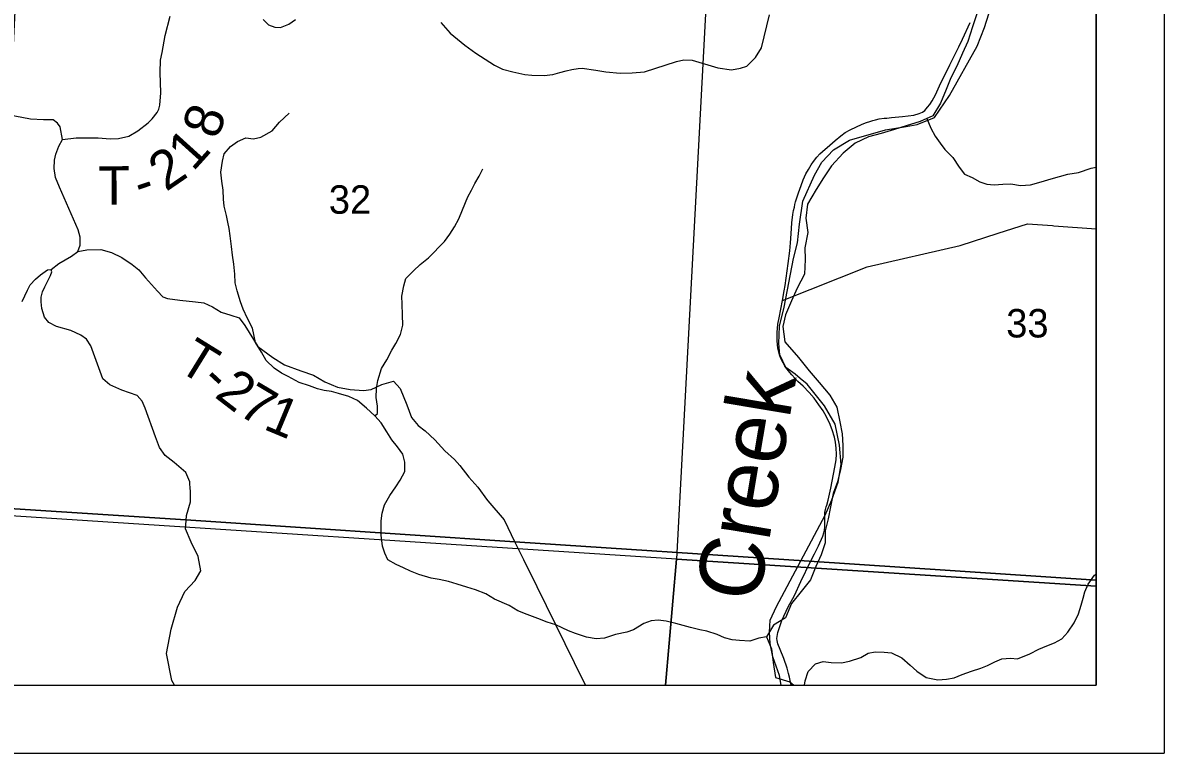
# Model space of a CAD drawing. Extents: x 0 to 44, y -23.8 to 22.
# Drawn here: x 7.321 to 9, y 14 to 15.074 of the extents above; entities that cross this region are included whole.
import ezdxf

# ---------------------------------------------------------------- set-up
doc = ezdxf.new("R2010")
doc.units = 0
for name, color, linetype in [('Default', 7, 'Continuous'), ('GM_X_County_Road', 7, 'Continuous'), ('GM_X_Minor_River', 7, 'Continuous'), ('GM_X_Minor_River_Text', 7, 'Continuous'), ('GM_X_Rail_Line', 7, 'Continuous'), ('GM_X_Section', 7, 'Continuous'), ('GM_X_Section_Text', 7, 'Continuous'), ('GM_X_State_Route', 7, 'Continuous'), ('GM_X_Township_Road', 7, 'Continuous'), ('GM_X_Township_Road_Text', 7, 'Continuous'), ('SH_Cut_Line', 7, 'Continuous'), ('SH_Data', 7, 'Continuous')]:
    doc.layers.add(name, color=color, linetype=linetype)

msp = doc.modelspace()

# ---------------------------------------------------------------- linework, layer by layer
at = {"layer": 'Default'}
msp.add_lwpolyline([(7.2787, 14.3616), (7.5613, 14.343), (8.045, 14.3111), (8.4778, 14.2825), (8.9, 14.2547), (8.9, 20.3521), (8.6785, 20.3684), (7.6577, 20.4476), (7.4495, 20.4611), (7.016, 20.4891)], dxfattribs=at)
for points in [[(8.9, 14.2455), (8.9, 15.2663), (8.3369, 15.3004), (8.2829, 14.2852)], [(7.2659, 14.1), (8.9, 14.1), (8.9, 14.2547), (8.4778, 14.2825), (8.045, 14.3111), (7.5613, 14.343), (7.2787, 14.3616)], [(7.2605, 14.1), (8.2666, 14.1), (8.2829, 14.2852), (7.2726, 14.3512)], [(8.2666, 14.1), (8.9, 14.1), (8.9, 14.2455), (8.2829, 14.2852)]]:
    msp.add_lwpolyline(points, close=True, dxfattribs=at)
at = {"layer": 'GM_X_County_Road'}
for points in [[(7.567, 14.3962), (7.5668, 14.3991), (7.5612, 14.4128), (7.5439, 14.4277), (7.5307, 14.4381), (7.5224, 14.4495), (7.5164, 14.4651), (7.5015, 14.5074), (7.4971, 14.5177), (7.4895, 14.5261), (7.4668, 14.5342), (7.4491, 14.5419), (7.4392, 14.5507), (7.4213, 14.5993), (7.4152, 14.6089), (7.4067, 14.615), (7.3918, 14.6215), (7.3711, 14.6276), (7.3596, 14.6334), (7.3531, 14.6414), (7.3492, 14.6541), (7.3482, 14.664), (7.3483, 14.6707), (7.3502, 14.6788), (7.3539, 14.6862), (7.3619, 14.7026), (7.3639, 14.708), (7.3632, 14.7117)], [(7.5445, 14.1), (7.5407, 14.1068), (7.5329, 14.1464), (7.5396, 14.1824), (7.5486, 14.2146), (7.5597, 14.2377), (7.5746, 14.254), (7.583, 14.268), (7.5794, 14.2893), (7.5689, 14.3106), (7.5607, 14.33), (7.5615, 14.3425), (7.562, 14.3494), (7.5678, 14.3699), (7.5679, 14.3847), (7.5675, 14.3905), (7.567, 14.3962)]]:
    msp.add_lwpolyline(points, dxfattribs=at)
at = {"layer": 'GM_X_Minor_River'}
for points in [[(8.7244, 15.0875), (8.7183, 15.0685), (8.7111, 15.0468), (8.7035, 15.0297), (8.6951, 15.0107), (8.6864, 14.9936), (8.6795, 14.9761), (8.6708, 14.9563), (8.6597, 14.9377), (8.6412, 14.9294), (8.6207, 14.9229), (8.6033, 14.9172), (8.584, 14.9115), (8.565, 14.9066), (8.5457, 14.8971), (8.5279, 14.8827), (8.5108, 14.8641), (8.499, 14.8462), (8.488, 14.8291), (8.4755, 14.8074), (8.4731, 14.7869), (8.4757, 14.766), (8.4715, 14.7435), (8.4719, 14.726), (8.4711, 14.7044), (8.4604, 14.6842), (8.4517, 14.6656), (8.4433, 14.6447), (8.4391, 14.6276), (8.4421, 14.6051), (8.4624, 14.5819), (8.4779, 14.5625), (8.4926, 14.5454), (8.5081, 14.5267), (8.5187, 14.5089), (8.5232, 14.4876), (8.5265, 14.4697), (8.5273, 14.4526), (8.5272, 14.4354), (8.5238, 14.4172), (8.5196, 14.3989), (8.5131, 14.3818), (8.5093, 14.3624), (8.5058, 14.3446), (8.5016, 14.3271), (8.5016, 14.3092), (8.4955, 14.2917), (8.4875, 14.2746), (8.4799, 14.2548), (8.4662, 14.2377), (8.4518, 14.2202), (8.443, 14.1993), (8.4256, 14.1883), (8.4153, 14.1712), (8.4225, 14.1533), (8.4251, 14.1332), (8.4284, 14.1115), (8.4492, 14.105), (8.4552, 14.1)], [(7.6608, 14.9038), (7.6714, 14.9061), (7.688, 14.9156), (7.699, 14.9281), (7.713, 14.9414)], [(8.6508, 14.9337), (8.657, 14.9196), (8.663, 14.9074), (8.6706, 14.8975), (8.6774, 14.888), (8.6891, 14.8762), (8.6985, 14.8618), (8.7064, 14.8515), (8.7174, 14.8469), (8.7287, 14.8404), (8.7393, 14.837), (8.7499, 14.8358), (8.7628, 14.8369), (8.7745, 14.8376), (8.7885, 14.8349), (8.8033, 14.836), (8.8192, 14.8405), (8.8339, 14.845), (8.8582, 14.8517), (8.8741, 14.8543), (8.8926, 14.8607), (8.9, 14.862)], [(8.4153, 14.1712), (8.4038, 14.1692), (8.3906, 14.1646), (8.3755, 14.1658), (8.3645, 14.1669), (8.3535, 14.1695), (8.3426, 14.1745), (8.3275, 14.1794), (8.3173, 14.1813), (8.3033, 14.1847), (8.2927, 14.1877), (8.2817, 14.1907), (8.2677, 14.1941), (8.2556, 14.1956), (8.2454, 14.1949), (8.2345, 14.1907), (8.2197, 14.1816), (8.2099, 14.1782), (8.1929, 14.1744), (8.177, 14.1694), (8.1645, 14.1683), (8.1506, 14.1705), (8.1343, 14.1762), (8.1237, 14.18), (8.1052, 14.1887), (8.0927, 14.1929), (8.0787, 14.1982), (8.0632, 14.2042), (8.0496, 14.2095), (8.0364, 14.2171), (8.0149, 14.2266), (8.0024, 14.2342), (7.9869, 14.2402), (7.9744, 14.2444), (7.9604, 14.2486), (7.9472, 14.2527), (7.9336, 14.2554), (7.9219, 14.2576), (7.9037, 14.2629), (7.8916, 14.2675), (7.8814, 14.2724), (7.8705, 14.2773), (7.8584, 14.2845), (7.8538, 14.2944), (7.8504, 14.3046), (7.8486, 14.3209), (7.8482, 14.3304), (7.8486, 14.3418), (7.8501, 14.3532), (7.8535, 14.3653), (7.861, 14.379), (7.8701, 14.3919), (7.8765, 14.4017), (7.8833, 14.4143), (7.8834, 14.4279), (7.8803, 14.4397), (7.8724, 14.4507), (7.8641, 14.4609), (7.8569, 14.4727), (7.8482, 14.4859), (7.8391, 14.4962), (7.827, 14.5075), (7.8134, 14.5189), (7.801, 14.5246), (7.7855, 14.5291), (7.7753, 14.5318), (7.7647, 14.5333), (7.7548, 14.5359), (7.7428, 14.5405), (7.7276, 14.5454), (7.7114, 14.5541), (7.7016, 14.559), (7.691, 14.5662), (7.6793, 14.5776), (7.6725, 14.5901), (7.6634, 14.6042), (7.6592, 14.625), (7.6517, 14.6394), (7.6453, 14.6531), (7.6415, 14.6637), (7.6366, 14.68), (7.6339, 14.6921), (7.6332, 14.7046), (7.6317, 14.7194), (7.6298, 14.7327), (7.6283, 14.7452), (7.6264, 14.7612), (7.6249, 14.7718), (7.623, 14.7813), (7.6211, 14.7911), (7.6173, 14.8044), (7.6166, 14.815), (7.6158, 14.8283), (7.6139, 14.8416), (7.6124, 14.8545), (7.6151, 14.8708), (7.6177, 14.8814), (7.6268, 14.8924), (7.637, 14.8996), (7.6491, 14.9053), (7.6608, 14.9038)], [(7.8391, 14.4962), (7.8429, 14.4996), (7.8429, 14.5106), (7.841, 14.5231), (7.8414, 14.5364), (7.8433, 14.5481), (7.849, 14.566), (7.8569, 14.5785), (7.8641, 14.5929), (7.8702, 14.6024), (7.8766, 14.6161), (7.8804, 14.6297), (7.88, 14.6449), (7.8792, 14.6604), (7.8789, 14.6722), (7.8815, 14.6874), (7.8849, 14.6984), (7.8959, 14.7097), (7.9057, 14.7189), (7.9178, 14.7287), (7.9416, 14.7526), (7.9496, 14.7633), (7.956, 14.7743), (7.9624, 14.786), (7.9681, 14.7993), (7.976, 14.8183), (7.9813, 14.8281), (7.9863, 14.838), (7.9927, 14.849), (7.998, 14.8596)], [(8.4712, 14.1), (8.4718, 14.1063), (8.4764, 14.1199), (8.4873, 14.1313), (8.4987, 14.1347), (8.5104, 14.1332), (8.5255, 14.1329), (8.5372, 14.1355), (8.5539, 14.1405), (8.5648, 14.1469), (8.5747, 14.1492), (8.5883, 14.1484), (8.5992, 14.1477), (8.614, 14.1401), (8.6265, 14.1295), (8.6363, 14.1208), (8.6499, 14.1113), (8.6669, 14.1079), (8.6801, 14.1087), (8.6911, 14.111), (8.7028, 14.1155), (8.7164, 14.1208), (8.7304, 14.125), (8.7402, 14.1292), (8.7508, 14.1345), (8.7614, 14.1387), (8.7739, 14.1398), (8.7845, 14.1387), (8.8022, 14.1459), (8.8158, 14.1528), (8.8276, 14.1581), (8.8389, 14.1623), (8.8495, 14.1683), (8.8582, 14.1782), (8.8676, 14.1919), (8.8741, 14.2048), (8.8778, 14.2177), (8.8809, 14.2279), (8.8835, 14.2374), (8.8881, 14.2488), (8.8975, 14.2617), (8.9, 14.2634)]]:
    msp.add_lwpolyline(points, dxfattribs=at)
at = {"layer": 'GM_X_Rail_Line'}
msp.add_lwpolyline([(8.4367, 14.1), (8.434, 14.1144), (8.4243, 14.1418), (8.4203, 14.1611), (8.4195, 14.178), (8.4203, 14.1957), (8.43, 14.2158), (8.5015, 14.3502), (8.5112, 14.3728), (8.5204, 14.3988), (8.5249, 14.4246), (8.5225, 14.4529), (8.5159, 14.4841), (8.5005, 14.5111), (8.4748, 14.5426), (8.4648, 14.5513), (8.4572, 14.5573), (8.4436, 14.5675), (8.4348, 14.586), (8.4333, 14.6026), (8.434, 14.6279), (8.4412, 14.6561), (8.4549, 14.7277), (8.4606, 14.7506), (8.4636, 14.7784), (8.4686, 14.8122), (8.4858, 14.8504), (8.4967, 14.8693), (8.5139, 14.8876), (8.5371, 14.9018), (8.5903, 14.9168), (8.6207, 14.922), (8.6365, 14.9249), (8.6624, 14.9353), (8.6841, 14.9675), (8.7252, 15.04), (8.7356, 15.0673), (8.7519, 15.1189)], dxfattribs=at)
at = {"layer": 'GM_X_Section'}
msp.add_lwpolyline([(8.3369, 15.3004), (8.2829, 14.2852), (7.2726, 14.3512), (7.3239, 15.368)], close=True, dxfattribs=at)
at = {"layer": 'GM_X_State_Route'}
for points in [[(7.3632, 14.7117), (7.3742, 14.7201), (7.3927, 14.7313), (7.4021, 14.738), (7.4058, 14.7474), (7.4058, 14.7589), (7.4029, 14.7699), (7.3751, 14.8326), (7.3693, 14.8466), (7.3673, 14.8602), (7.368, 14.8723), (7.3699, 14.8811), (7.3742, 14.893), (7.3797, 14.9029), (7.3763, 14.9215), (7.3723, 14.9269), (7.3662, 14.9316), (7.3517, 14.9316), (7.3328, 14.9327), (7.2757, 14.9436)], [(7.3206, 14.6643), (7.328, 14.6811), (7.332, 14.6887), (7.3401, 14.6971), (7.3473, 14.7034), (7.3576, 14.7108), (7.3632, 14.7117)]]:
    msp.add_lwpolyline(points, dxfattribs=at)
at = {"layer": 'GM_X_Township_Road'}
for p, q in [((8.8379, 14.7758), (8.9, 14.7715)), ((8.0912, 14.217), (8.1461, 14.1054)), ((8.1461, 14.1054), (8.1487, 14.1))]:
    msp.add_line(p, q, dxfattribs=at)
for points in [[(7.3797, 14.9029), (7.4, 14.9053), (7.432, 14.9053), (7.4498, 14.9035), (7.4623, 14.9041), (7.4772, 14.9075), (7.4906, 14.9153), (7.5058, 14.9272), (7.5115, 14.9331), (7.5188, 14.9424), (7.5216, 14.9474), (7.5228, 14.9533), (7.5245, 14.9712), (7.5232, 15.0013), (7.5239, 15.0192), (7.5262, 15.0305), (7.5305, 15.0557), (7.5381, 15.0842)], [(7.675, 15.0792), (7.6829, 15.0713), (7.692, 15.068), (7.7004, 15.0674), (7.7124, 15.0725), (7.7222, 15.0791)], [(7.936, 15.0749), (7.9501, 15.0591), (7.9714, 15.0417), (7.9877, 15.0297), (8.0149, 15.0118), (8.0266, 15.0061), (8.0422, 15.0024), (8.0598, 14.9984), (8.0702, 14.9971), (8.0883, 14.9966), (8.101, 14.9982), (8.1114, 15.0011), (8.1204, 15.0038), (8.1289, 15.0056), (8.1383, 15.0072), (8.1438, 15.0074), (8.1643, 15.0045), (8.179, 15.002), (8.1998, 15.0001), (8.2175, 15.0007), (8.2359, 15.0022), (8.2829, 15.0172), (8.2937, 15.0199), (8.3059, 15.0196), (8.3437, 15.0082), (8.3638, 15.0052), (8.377, 15.0074), (8.386, 15.0107), (8.3988, 15.0231), (8.408, 15.0373), (8.4195, 15.0861)], [(8.4658, 14.2524), (8.4797, 14.2819), (8.4856, 14.2931), (8.4918, 14.305), (8.498, 14.3192), (8.4996, 14.3243), (8.5003, 14.3279), (8.5007, 14.3331), (8.5008, 14.3418), (8.5008, 14.3497), (8.501, 14.354), (8.502, 14.3585), (8.5027, 14.3626), (8.5037, 14.365), (8.5056, 14.3724), (8.5098, 14.39), (8.5157, 14.4205), (8.5177, 14.4316), (8.518, 14.44), (8.5178, 14.4488), (8.5167, 14.4575), (8.5149, 14.465), (8.5117, 14.4756), (8.5079, 14.4859), (8.501, 14.4992), (8.4985, 14.5035), (8.4923, 14.5125), (8.4854, 14.522), (8.4777, 14.5303), (8.4689, 14.5397), (8.4613, 14.5467), (8.4567, 14.5518), (8.4524, 14.5563), (8.4492, 14.5602), (8.4453, 14.565), (8.4423, 14.5695), (8.4394, 14.5743), (8.4363, 14.5806), (8.4342, 14.5861), (8.4319, 14.5959), (8.4312, 14.6011), (8.4308, 14.6064), (8.4306, 14.6101), (8.4306, 14.614), (8.4307, 14.6187), (8.4311, 14.6253), (8.4319, 14.6312), (8.4337, 14.6403), (8.4386, 14.6658), (8.4412, 14.6799), (8.4425, 14.6881), (8.4456, 14.7096), (8.4471, 14.7203), (8.4493, 14.7388), (8.4505, 14.7505), (8.4514, 14.7639), (8.4525, 14.78), (8.454, 14.7923), (8.455, 14.7985), (8.4562, 14.8034), (8.457, 14.8071), (8.458, 14.8108), (8.4624, 14.8242), (8.4662, 14.8348), (8.4692, 14.8432), (8.473, 14.8521), (8.4767, 14.8587), (8.4806, 14.8653), (8.4842, 14.8705), (8.4892, 14.8767), (8.4937, 14.8816), (8.5012, 14.8885), (8.5044, 14.8911), (8.5163, 14.9014), (8.5245, 14.9082), (8.5309, 14.9128), (8.5381, 14.9169), (8.556, 14.9255), (8.562, 14.9278), (8.5669, 14.9293), (8.5713, 14.9306), (8.5753, 14.9317), (8.581, 14.9329), (8.5883, 14.9339), (8.592, 14.9343), (8.5991, 14.9349), (8.6149, 14.9365), (8.6317, 14.9387), (8.6398, 14.9409), (8.6444, 14.9431), (8.6482, 14.9454), (8.6521, 14.9502), (8.6555, 14.954), (8.659, 14.9595), (8.6637, 14.9686), (8.6697, 14.9816), (8.6849, 15.0127), (8.6978, 15.039), (8.7033, 15.0505), (8.7149, 15.0747)], [(8.4386, 14.6658), (8.5634, 14.7155), (8.7001, 14.747), (8.756, 14.7649), (8.7989, 14.7786), (8.836, 14.776), (8.8379, 14.7758)], [(7.4021, 14.738), (7.4157, 14.7405), (7.4361, 14.7407), (7.4516, 14.7365), (7.4669, 14.729), (7.4824, 14.719), (7.4918, 14.711), (7.5018, 14.6993), (7.5194, 14.6797), (7.5273, 14.6713), (7.534, 14.6686), (7.5524, 14.6664), (7.5754, 14.6641), (7.5877, 14.6625), (7.6003, 14.6564), (7.6133, 14.6487), (7.6275, 14.6445), (7.6394, 14.6403), (7.6479, 14.6292), (7.6671, 14.5983), (7.689, 14.5818), (7.706, 14.5711), (7.7302, 14.5626), (7.7491, 14.556), (7.7654, 14.546), (7.7843, 14.5383), (7.8029, 14.5348), (7.8222, 14.5335), (7.8336, 14.535), (7.8496, 14.5425), (7.8663, 14.5473), (7.8761, 14.5366), (7.8861, 14.5126), (7.8929, 14.494), (7.9026, 14.4821), (7.9132, 14.4741), (7.9275, 14.4611), (7.9422, 14.4447), (7.9562, 14.4321), (7.9641, 14.4233), (7.9772, 14.4061), (7.9904, 14.3912), (8.0047, 14.3718), (8.0053, 14.3711), (8.0292, 14.3431), (8.0452, 14.3106), (8.0578, 14.285), (8.0772, 14.2454), (8.0912, 14.217)], [(8.4513, 14.1), (8.4504, 14.1044), (8.4489, 14.1116), (8.4477, 14.1171), (8.4455, 14.1252), (8.4404, 14.1391), (8.435, 14.1526), (8.4317, 14.1606), (8.4306, 14.1656), (8.4303, 14.1685), (8.4308, 14.1715), (8.4318, 14.1774), (8.4345, 14.1864), (8.4378, 14.1954), (8.447, 14.2151), (8.4562, 14.2319), (8.4658, 14.2524)]]:
    msp.add_lwpolyline(points, dxfattribs=at)
at = {"layer": 'SH_Cut_Line'}
msp.add_lwpolyline([(2.838, 14.1), (8.9, 14.1), (8.9, 20.9), (6.8158, 20.9)], dxfattribs=at)
at = {"layer": 'SH_Data'}
for p, q in [((9, 21), (9, 14)), ((8.9, 20.9), (8.9, 14.1)), ((2.1, 14.1), (8.9, 14.1)), ((2, 14), (9, 14))]:
    msp.add_line(p, q, dxfattribs=at)

# ---------------------------------------------------------------- texts
at = {"layer": 'GM_X_Minor_River_Text'}
msp.add_text('Creek', height=0.0947, rotation=80.4921, dxfattribs=at).set_placement((8.4035, 14.2196))
at = {"layer": 'GM_X_Section_Text'}
for s, p in [('32', (7.7714, 14.7935)), ('33', (8.7677, 14.6115))]:
    msp.add_text(s, height=0.04186, rotation=0, dxfattribs=at).set_placement(p)
at = {"layer": 'GM_X_Township_Road_Text'}
for s, rotation, p in [('8', 70.5365, (7.6076, 14.9014)), ('1', 47.9064, (7.5717, 14.8545)), ('2', 34.4311, (7.5319, 14.8252)), ('T', 0.2829, (7.4326, 14.8065)), ('-', 18.9527, (7.4949, 14.8101)), ('T', 328.2667, (7.5466, 14.5649)), ('-', 317.1587, (7.5804, 14.5443)), ('2', 322.4255, (7.6018, 14.5248)), ('7', 329.2123, (7.6357, 14.4993)), ('1', 337.3284, (7.6735, 14.4775))]:
    msp.add_text(s, height=0.0568, rotation=rotation, dxfattribs=at).set_placement(p)

doc.saveas('drawing.dxf')
